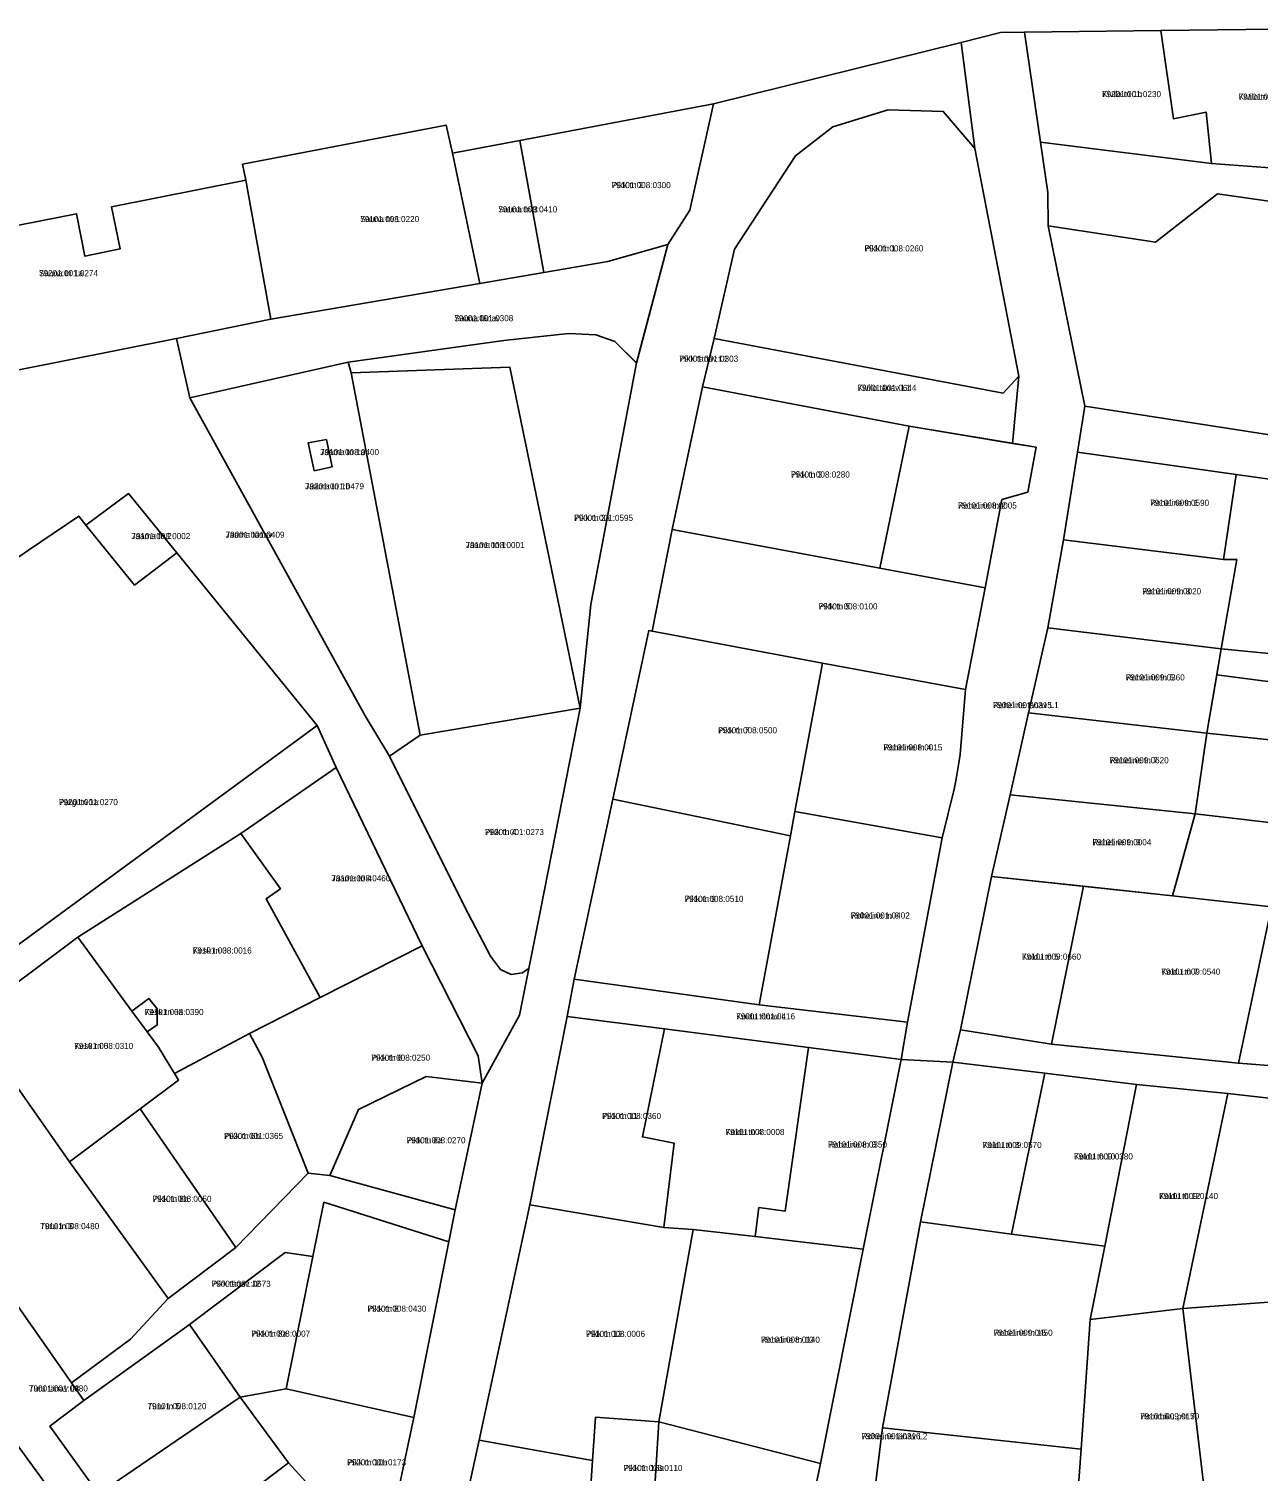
# Model space of a CAD drawing. Extents: x 587616 to 632239, y 6547421 to 6574977.
# Drawn here: x 611846.3 to 612148.7, y 6570989.5 to 6571344.3 of the extents above; entities that cross this region are included whole.
import ezdxf

# ---------------------------------------------------------------- set-up
doc = ezdxf.new("R2010")
doc.units = 0
for name, color, linetype in [('L_AADRESS', 7, 'Continuous'), ('PIIR', 7, 'Continuous'), ('TUNNUS', 7, 'Continuous')]:
    doc.layers.add(name, color=color, linetype=linetype)

msp = doc.modelspace()

# ---------------------------------------------------------------- linework, layer by layer
at = {"layer": 'PIIR'}
for points in [[(612159.63, 6571344.34), (612124.75, 6571343.9), (612091.19, 6571343.49), (612085.34, 6571343.42), (612075.6, 6571341), (612014.71, 6571325.9), (611967.08, 6571316.89), (611950.53, 6571313.76), (611948.93, 6571320.68), (611898.86, 6571311.01), (611899.64, 6571307.09), (611866.62, 6571300.55), (611868.7, 6571290.18), (611860.08, 6571288.4), (611857.99, 6571298.86), (611793.18, 6571286.08), (611716.96, 6571271.05), (611686.66, 6571259.35), (611655.98, 6571247.48), (611408.02, 6571196), (611286.97, 6571135.57), (611224.5, 6571123.76), (611132.41, 6571106.34)], [(611934.47, 6570972.06), (611940.95, 6571002.62), (611949.58, 6571045.84), (611951.18, 6571053.73), (611957.8, 6571084.94), (611966.95, 6571101.66), (611969.27, 6571113.14), (611972.25, 6571127.9), (611981.93, 6571177.16), (611984.57, 6571202.68), (611995.77, 6571262.19), (612003.5, 6571291.27), (612008.92, 6571299.72), (612014.71, 6571325.9), (612075.6, 6571341), (612079.03, 6571314.89), (612071.23, 6571324), (612057.68, 6571324.43), (612044.08, 6571320.27), (612034.89, 6571313.06), (612019.91, 6571290.15), (612014.85, 6571268.18), (612011.99, 6571256.26), (612004.56, 6571221.13), (611999.58, 6571196.13), (611998.79, 6571196.26), (611989.91, 6571154.82), (611980.45, 6571110.48), (611978.73, 6571101.33), (611969.53, 6571054.97), (611957.02, 6570997.08), (611949.31, 6570961.41)], [(612225.36, 6571291.39), (612138.73, 6571303.77), (612123.46, 6571291.85), (612097.01, 6571295.89), (612096.94, 6571304.04), (612095.13, 6571316.44), (612137.22, 6571311.19), (612161.56, 6571309.44)], [(611840.92, 6571259.86), (611882.6, 6571268.16), (611885.88, 6571253.53), (611929.02, 6571175.32), (611935.02, 6571165.42), (611953.43, 6571128.42), (611959.81, 6571116.13), (611962.28, 6571112.89), (611964.94, 6571111.65), (611967.61, 6571112.03), (611969.27, 6571113.14), (611966.95, 6571101.66), (611957.8, 6571084.94), (611956.82, 6571091.68), (611943.03, 6571118.7), (611921.84, 6571162.58), (611917.24, 6571172.94), (611882.65, 6571215.41), (611870.8, 6571229.97), (611860.33, 6571222.25), (611858.54, 6571224.47), (611846.22, 6571216.07)], [(612162.03, 6571232.07), (612143.29, 6571234.7), (612104.25, 6571240.15), (612106.04, 6571251.52), (612176.89, 6571240.53)], [(611596.46, 6570962.66), (611673.74, 6570998.74), (611694.36, 6571008.59), (611717.91, 6571025.71), (611724.56, 6571030.16), (611783.89, 6571075.21), (611793.48, 6571082.19), (611917.24, 6571172.94), (611921.84, 6571162.58), (611898.4, 6571146.35), (611858.29, 6571120.81), (611831.79, 6571100.99), (611806.97, 6571082.36), (611790.89, 6571067.49), (611746.86, 6571034.54), (611745.56, 6571036.48), (611716.21, 6571014.5), (611694, 6570998.65), (611656.11, 6570977.68)], [(612168.14, 6571079.36), (612141.26, 6571082.37), (612118.78, 6571084.6), (612096.24, 6571087.37), (612073.58, 6571090.09), (612075.45, 6571098.01), (612097.83, 6571094.53), (612143.83, 6571089.87), (612165.05, 6571088.21)]]:
    msp.add_lwpolyline(points, dxfattribs=at)
for points in [[(612091.19, 6571343.49), (612124.75, 6571343.9), (612127.87, 6571322.2), (612135.9, 6571323.86), (612137.22, 6571311.19), (612095.13, 6571316.44)], [(612159.63, 6571344.34), (612161.56, 6571309.44), (612137.22, 6571311.19), (612135.9, 6571323.86), (612127.87, 6571322.2), (612124.75, 6571343.9)], [(612075.6, 6571341), (612085.34, 6571343.42), (612091.19, 6571343.49), (612095.13, 6571316.44), (612096.94, 6571304.04), (612097.01, 6571295.89), (612106.04, 6571251.52), (612104.25, 6571240.15), (612100.81, 6571218.65), (612096.94, 6571196.98), (612092.17, 6571176.07), (612087.66, 6571155.9), (612083.07, 6571135.78), (612075.45, 6571098.01), (612073.58, 6571090.09), (612060.85, 6571090.75), (612062.4, 6571099.89), (612071, 6571145.29), (612073.95, 6571157.25), (612074.3, 6571159.32), (612075.06, 6571163.71), (612075.41, 6571165.77), (612076.7, 6571181.82), (612081.51, 6571206.81), (612085.65, 6571228.52), (612092, 6571230.37), (612094.06, 6571241.4), (612088.25, 6571242.34), (612089.83, 6571258.89), (612079.03, 6571314.89)], [(612014.71, 6571325.9), (612008.92, 6571299.72), (612003.5, 6571291.27), (611988.74, 6571287.06), (611972.99, 6571284.39), (611967.08, 6571316.89)], [(612019.91, 6571290.15), (612034.89, 6571313.06), (612044.08, 6571320.27), (612057.68, 6571324.43), (612071.23, 6571324), (612079.03, 6571314.89), (612089.83, 6571258.89), (612085.97, 6571254.71), (612014.85, 6571268.18)], [(611898.86, 6571311.01), (611948.93, 6571320.68), (611950.53, 6571313.76), (611957.26, 6571281.67), (611905.83, 6571272.89), (611899.64, 6571307.09)], [(611950.53, 6571313.76), (611967.08, 6571316.89), (611972.99, 6571284.39), (611957.26, 6571281.67)], [(611793.18, 6571286.08), (611857.99, 6571298.86), (611860.08, 6571288.4), (611868.7, 6571290.18), (611866.62, 6571300.55), (611899.64, 6571307.09), (611905.83, 6571272.89), (611882.6, 6571268.16), (611840.92, 6571259.86), (611828.55, 6571263.66), (611813.81, 6571271.14), (611804.44, 6571276), (611795.74, 6571278.98), (611794.13, 6571280.68)], [(612106.04, 6571251.52), (612097.01, 6571295.89), (612123.46, 6571291.85), (612138.73, 6571303.77), (612225.36, 6571291.39), (612223.39, 6571278.76), (612176.89, 6571240.53)], [(612003.5, 6571291.27), (611995.75, 6571262.11), (611990.43, 6571267.37), (611985.73, 6571269.08), (611979.04, 6571269.37), (611963.13, 6571267.64), (611924.82, 6571262.32), (611885.88, 6571253.53), (611882.6, 6571268.16), (611905.83, 6571272.89), (611957.26, 6571281.67), (611972.99, 6571284.39), (611988.74, 6571287.06)], [(611925.53, 6571259.72), (611924.82, 6571262.32), (611963.13, 6571267.64), (611979.04, 6571269.37), (611985.73, 6571269.08), (611990.43, 6571267.37), (611995.77, 6571262.19), (611984.57, 6571202.68), (611981.93, 6571177.16), (611964.57, 6571261.13)], [(612014.85, 6571268.18), (612085.97, 6571254.71), (612089.83, 6571258.89), (612088.25, 6571242.34), (612062.85, 6571246.54), (612011.99, 6571256.26)], [(611935.02, 6571165.42), (611929.02, 6571175.32), (611885.88, 6571253.53), (611924.82, 6571262.32), (611925.53, 6571259.72), (611942.56, 6571170.55)], [(611925.53, 6571259.72), (611964.57, 6571261.13), (611981.93, 6571177.16), (611942.56, 6571170.55)], [(612011.99, 6571256.26), (612062.85, 6571246.54), (612055.6, 6571211.61), (612004.56, 6571221.13)], [(612062.85, 6571246.54), (612094.06, 6571241.4), (612092, 6571230.37), (612085.65, 6571228.52), (612081.51, 6571206.81), (612055.6, 6571211.61)], [(611919.49, 6571243.26), (611920.89, 6571236.55), (611916.47, 6571235.62), (611914.98, 6571242.44)], [(611920.89, 6571236.55), (611919.49, 6571243.26), (611914.98, 6571242.44), (611916.47, 6571235.62)], [(612104.25, 6571240.15), (612143.29, 6571234.7), (612140.2, 6571213.8), (612100.81, 6571218.65)], [(612143.44, 6571213.75), (612140.2, 6571213.8), (612143.29, 6571234.7), (612162.03, 6571232.07), (612154.8, 6571190.35), (612139.63, 6571191.77)], [(611870.8, 6571229.97), (611882.65, 6571215.41), (611872.27, 6571207.47), (611860.33, 6571222.25)], [(611796.12, 6571181.57), (611846.22, 6571216.07), (611858.54, 6571224.47), (611860.33, 6571222.25), (611872.27, 6571207.47), (611882.65, 6571215.41), (611917.24, 6571172.94), (611793.48, 6571082.19), (611746.37, 6571145.45), (611778.84, 6571168.84), (611817.45, 6571116.23), (611834.77, 6571128.93)], [(612076.7, 6571181.82), (612041.51, 6571188.29), (611999.58, 6571196.13), (612004.56, 6571221.13), (612055.6, 6571211.61), (612081.51, 6571206.81)], [(612100.81, 6571218.65), (612140.2, 6571213.8), (612143.44, 6571213.75), (612139.63, 6571191.77), (612096.94, 6571196.98)], [(611998.79, 6571196.26), (611999.58, 6571196.13), (612041.51, 6571188.29), (612034.75, 6571151.78), (612033.64, 6571145.75), (611989.91, 6571154.82)], [(612096.94, 6571196.98), (612139.63, 6571191.77), (612136.06, 6571171.04), (612092.17, 6571176.07)], [(612139.63, 6571191.77), (612154.8, 6571190.35), (612169.4, 6571188.56), (612168.18, 6571181.54), (612138.54, 6571185.42)], [(612041.51, 6571188.29), (612076.7, 6571181.82), (612075.41, 6571165.77), (612075.06, 6571163.71), (612074.3, 6571159.32), (612073.95, 6571157.25), (612071, 6571145.29), (612034.75, 6571151.78)], [(612138.54, 6571185.42), (612168.18, 6571181.54), (612169.4, 6571188.56), (612183.24, 6571187.09), (612185.26, 6571186.86), (612181.01, 6571166.26), (612136.1, 6571171.05)], [(611935.02, 6571165.42), (611942.56, 6571170.55), (611981.93, 6571177.16), (611972.25, 6571127.9), (611969.27, 6571113.14), (611967.61, 6571112.03), (611964.94, 6571111.65), (611962.28, 6571112.89), (611959.81, 6571116.13), (611953.43, 6571128.42)], [(612092.17, 6571176.07), (612136.06, 6571171.04), (612133.18, 6571151.19), (612087.66, 6571155.9)], [(612176.78, 6571146.09), (612133.18, 6571151.19), (612136.06, 6571171.04), (612180.96, 6571166.26)], [(611904.64, 6571130.26), (611908.16, 6571132.77), (611898.4, 6571146.35), (611921.84, 6571162.58), (611943.03, 6571118.7), (611917.93, 6571105.96)], [(612083.07, 6571135.78), (612087.66, 6571155.9), (612133.18, 6571151.19), (612127.6, 6571131.03)], [(611989.91, 6571154.82), (612033.64, 6571145.75), (612025.98, 6571104.21), (611980.45, 6571110.48)], [(612033.64, 6571145.75), (612034.75, 6571151.78), (612071, 6571145.29), (612062.4, 6571099.89), (612025.98, 6571104.21)], [(612127.6, 6571131.03), (612133.18, 6571151.19), (612176.78, 6571146.09), (612173.72, 6571125.87), (612152, 6571128.31)], [(611898.4, 6571146.35), (611908.16, 6571132.77), (611904.64, 6571130.26), (611917.93, 6571105.96), (611900.56, 6571097.15), (611882.14, 6571087.28), (611878.17, 6571093.77), (611875.41, 6571097.52), (611877.86, 6571099.25), (611877.88, 6571103.19), (611875.82, 6571105.75), (611871.64, 6571102.65), (611858.29, 6571120.81)], [(612083.07, 6571135.78), (612105.76, 6571133.36), (612097.83, 6571094.53), (612075.45, 6571098.01)], [(612105.76, 6571133.36), (612127.6, 6571131.03), (612152, 6571128.31), (612143.83, 6571089.87), (612097.83, 6571094.53)], [(612152, 6571128.31), (612173.72, 6571125.87), (612165.05, 6571088.21), (612143.83, 6571089.87)], [(611842.9, 6571084.7), (611831.79, 6571100.99), (611858.29, 6571120.81), (611871.64, 6571102.65), (611875.41, 6571097.52), (611878.17, 6571093.77), (611882.14, 6571087.28), (611883.13, 6571085.66), (611873.63, 6571078.61), (611856.27, 6571065.58)], [(611903.65, 6571091.31), (611900.56, 6571097.15), (611917.93, 6571105.96), (611943.03, 6571118.7), (611956.82, 6571091.68), (611957.8, 6571084.94), (611944.06, 6571086.53), (611927.36, 6571078.47), (611920.34, 6571062.2), (611915.01, 6571062.81)], [(611980.45, 6571110.48), (612025.97, 6571104.21), (612062.4, 6571099.89), (612060.85, 6571090.75), (612038.12, 6571093.7), (612002.62, 6571098.26), (611978.73, 6571101.33)], [(611871.64, 6571102.65), (611875.82, 6571105.75), (611877.88, 6571103.19), (611877.86, 6571099.25), (611875.41, 6571097.52)], [(612002.62, 6571098.26), (611997.23, 6571071.68), (612005.06, 6571070.12), (612002.48, 6571049.41), (611969.53, 6571054.97), (611978.73, 6571101.33)], [(611915.01, 6571062.81), (611897.16, 6571044.45), (611873.63, 6571078.61), (611883.13, 6571085.66), (611882.14, 6571087.28), (611900.56, 6571097.15), (611903.65, 6571091.31)], [(612002.62, 6571098.26), (612038.12, 6571093.7), (612032.37, 6571053.43), (612025.9, 6571054.31), (612024.93, 6571047.15), (612009.68, 6571048.91), (612002.48, 6571049.41), (612005.06, 6571070.12), (611997.23, 6571071.68)], [(612060.85, 6571090.75), (612051.56, 6571044.07), (612024.93, 6571047.15), (612025.9, 6571054.31), (612032.37, 6571053.43), (612038.12, 6571093.7)], [(612060.85, 6571090.75), (612073.58, 6571090.09), (612065.63, 6571050.81), (612056.31, 6571000.15), (612052.02, 6570965.62), (612052.46, 6570959.45), (612053.64, 6570954.9), (612028.71, 6570932.34), (612041.01, 6570991.37), (612051.56, 6571044.07)], [(612073.58, 6571090.09), (612096.24, 6571087.37), (612087.99, 6571047.78), (612065.63, 6571050.81)], [(611842.9, 6571084.7), (611856.27, 6571065.58), (611880.56, 6571031.96), (611871.3, 6571021.89), (611856.76, 6571011.2), (611817.61, 6571067.01)], [(611920.34, 6571062.2), (611927.36, 6571078.47), (611944.06, 6571086.53), (611957.8, 6571084.94), (611951.18, 6571053.73)], [(612096.24, 6571087.37), (612118.78, 6571084.6), (612110.97, 6571044.82), (612087.99, 6571047.78)], [(612110.97, 6571044.82), (612118.78, 6571084.6), (612141.26, 6571082.37), (612130.2, 6571029.46), (612107.41, 6571026.75)], [(611790.89, 6571067.49), (611806.97, 6571082.36), (611817.61, 6571067.01), (611856.76, 6571011.2), (611859.81, 6571006.84), (611851.44, 6571000.55), (611863.4, 6570983.87), (611876.72, 6570966.16), (611901.68, 6570932.17), (611890.97, 6570930.92), (611875.82, 6570951.44), (611831.96, 6571011.62), (611818.65, 6571029.46)], [(612141.26, 6571082.37), (612168.14, 6571079.36), (612160.19, 6571031.69), (612130.2, 6571029.46)], [(611873.63, 6571078.61), (611897.16, 6571044.45), (611880.56, 6571031.96), (611856.27, 6571065.58)], [(611951.18, 6571053.73), (611949.58, 6571045.84), (611918.83, 6571055.61), (611916.14, 6571042.29), (611909.32, 6571043.26), (611885.83, 6571025.53), (611885.17, 6571025.05), (611859.81, 6571006.84), (611856.76, 6571011.2), (611871.3, 6571021.89), (611880.56, 6571031.96), (611897.16, 6571044.45), (611915.01, 6571062.81), (611920.34, 6571062.2)], [(611949.58, 6571045.84), (611940.95, 6571002.62), (611909.57, 6571009.68), (611916.14, 6571042.29), (611918.83, 6571055.61)], [(611969.53, 6571054.97), (612002.48, 6571049.41), (612009.68, 6571048.91), (612001.23, 6571001.62), (611985.7, 6571002.71), (611984.97, 6570992.06), (611957.02, 6570997.08)], [(612105.13, 6570994.86), (612056.31, 6571000.15), (612065.63, 6571050.81), (612087.99, 6571047.78), (612110.97, 6571044.82), (612107.41, 6571026.75)], [(612009.68, 6571048.91), (612024.93, 6571047.15), (612051.56, 6571044.07), (612041.01, 6570991.37), (612001.23, 6571001.62)], [(611885.83, 6571025.53), (611909.32, 6571043.26), (611916.14, 6571042.29), (611909.57, 6571009.68), (611898.26, 6571007.64)], [(612130.2, 6571029.46), (612160.19, 6571031.69), (612162.16, 6571031.85), (612167.56, 6570988.8), (612135.94, 6570980.88)], [(612135.94, 6570980.88), (612103.45, 6570971.53), (612105.13, 6570994.86), (612107.41, 6571026.75), (612130.2, 6571029.46)], [(611851.44, 6571000.55), (611859.81, 6571006.84), (611885.17, 6571025.05), (611885.83, 6571025.53), (611898.26, 6571007.64), (611863.4, 6570983.87)], [(611795.39, 6570960.29), (611811.73, 6570971.84), (611816.22, 6570999.65), (611831.96, 6571011.62), (611875.82, 6570951.44), (611843.11, 6570927.07), (611840.96, 6570929.94), (611836.93, 6570926.92), (611824.35, 6570917.49)], [(611910.15, 6570991.48), (611894.33, 6570979.5), (611876.72, 6570966.16), (611863.4, 6570983.87), (611898.26, 6571007.64)], [(611940.95, 6571002.62), (611934.47, 6570972.06), (611926.45, 6570973.62), (611910.15, 6570991.48), (611898.26, 6571007.64), (611909.57, 6571009.68)], [(611984.97, 6570992.06), (611985.7, 6571002.71), (612001.23, 6571001.62), (611999.74, 6570976.44), (611983.93, 6570977.11)], [(612001.23, 6571001.62), (612041.01, 6570991.37), (612028.71, 6570932.34), (612024.75, 6570928.62), (612018.15, 6570929.92), (612003.68, 6570932.78), (612011.99, 6570975.43), (611999.74, 6570976.44)], [(612103.45, 6570971.53), (612053.64, 6570954.9), (612052.46, 6570959.45), (612052.02, 6570965.62), (612054.9, 6570988.79), (612056.31, 6571000.15), (612105.13, 6570994.86)], [(611949.31, 6570961.41), (611957.02, 6570997.08), (611984.97, 6570992.06), (611983.93, 6570977.11), (611965.98, 6570957.18), (611950.81, 6570957.97)], [(611910.15, 6570991.48), (611926.45, 6570973.62), (611934.47, 6570972.06), (611937.58, 6570971.4), (611933.53, 6570951.02), (611931.49, 6570948.39), (611917.69, 6570942.27), (611894.33, 6570979.5)]]:
    msp.add_lwpolyline(points, close=True, dxfattribs=at)

# ---------------------------------------------------------------- texts
at = {"layer": 'L_AADRESS'}
for s, p in [('Kivilo tn 1b', (612110.31, 6571327.54)), ('Kivilo tn 1', (612143.9, 6571326.89)), ('Pikk tn 2', (611989.67, 6571305.15)), ('Sauna tn 1', (611927.8, 6571296.79)), ('Sauna tn 3', (611961.76, 6571299.17)), ('Pikk tn 1', (612051.84, 6571289.57)), ('Sauna tn 1a', (611848.78, 6571283.48)), ('Sauna tänav', (611950.95, 6571272.4)), ('Pikk tänav L1', (612006.28, 6571262.43)), ('Kivilo tänav L1', (612050.14, 6571255.26)), ('Jaama tn 1a', (611917.93, 6571239.45)), ('Pikk tn 3', (612033.75, 6571233.94)), ('Jaama tn 1b', (611914.22, 6571231.04)), ('Roheline tn 2', (612074.83, 6571226.31)), ('Roheline tn 1', (612122.14, 6571226.98)), ('Pikk tn 2a', (611980.42, 6571223.27)), ('Jaama tn 2', (611871.49, 6571218.78)), ('Jaama tänav', (611894.67, 6571219.12)), ('Jaama tn 1', (611953.73, 6571216.58)), ('Roheline tn 3', (612120.18, 6571205.21)), ('Pikk tn 5', (612040.56, 6571201.48)), ('Roheline tn 5', (612116.14, 6571184.01)), ('Roheline tänav L1', (612083.45, 6571177.19)), ('Pikk tn 7', (612015.84, 6571171.01)), ('Roheline tn 4', (612056.51, 6571166.79)), ('Roheline tn 7', (612112.19, 6571163.63)), ('Pargi tn 1a', (611853.68, 6571153.33)), ('Pikk tn 4', (611958.48, 6571145.96)), ('Roheline tn 9', (612107.93, 6571143.46)), ('Jaama tn 4', (611920.71, 6571134.59)), ('Pikk tn 9', (612007.58, 6571129.52)), ('Roheline tn 6', (612048.49, 6571125.43)), ('Kesk tn 3', (611886.61, 6571116.82)), ('Koidu tn 5', (612090.61, 6571115.31)), ('Koidu tn 7', (612124.89, 6571111.62)), ('Kesk tn 3a', (611874.76, 6571101.68)), ('Koidu tänav L1', (612020.29, 6571100.62)), ('Kesk tn 5', (611857.46, 6571093.33)), ('Pikk tn 6', (611930.5, 6571090.45)), ('Pikk tn 11', (611987.3, 6571076.1)), ('Pikk tn 6b', (611894.32, 6571071.19)), ('Pikk tn 6a', (611939.21, 6571070.13)), ('Koidu tn 4', (612017.67, 6571072.16)), ('Roheline tn 8', (612042.89, 6571069.08)), ('Koidu tn 8', (612080.94, 6571068.97)), ('Koidu tn 10', (612103.39, 6571066.14)), ('Pikk tn 8b', (611876.71, 6571055.71)), ('Koidu tn 12', (612124.33, 6571056.41)), ('Turu tn 3', (611849.09, 6571049)), ('Pikk tänav J2', (611891.26, 6571034.82)), ('Pikk tn 8', (611929.57, 6571028.69)), ('Roheline tn 15', (612083.64, 6571022.78)), ('Pikk tn 8a', (611900.98, 6571022.55)), ('Pikk tn 13', (611983.35, 6571022.49)), ('Roheline tn 10', (612026.39, 6571021.06)), ('Turu tänav L3', (611846.29, 6571009.05)), ('Turu tn 5', (611875.46, 6571004.7)), ('Hommiku pst 5', (612119.7, 6571002.21)), ('Roheline tänav L2', (612051.14, 6570997.32)), ('Pikk tn 10a', (611924.58, 6570990.87)), ('Pikk tn 15a', (611992.58, 6570989.49))]:
    msp.add_text(s, height=1.5, dxfattribs=at).set_placement(p)
at = {"layer": 'TUNNUS'}
for s, p in [('79201:001:0230', (612110.31, 6571327.54)), ('79101:009:0003', (612143.9, 6571326.89)), ('79101:008:0300', (611989.67, 6571305.15)), ('79101:008:0220', (611927.8, 6571296.79)), ('79101:008:0410', (611961.76, 6571299.17)), ('79101:008:0260', (612051.84, 6571289.57)), ('79201:001:0274', (611848.78, 6571283.48)), ('79001:001:0308', (611950.95, 6571272.4)), ('79001:001:0303', (612006.28, 6571262.43)), ('79001:001:0644', (612050.14, 6571255.26)), ('79101:008:0400', (611917.93, 6571239.45)), ('79101:008:0280', (612033.75, 6571233.94)), ('79201:001:0479', (611914.22, 6571231.04)), ('79101:008:0005', (612074.83, 6571226.31)), ('79101:009:0590', (612122.14, 6571226.98)), ('79001:001:0595', (611980.42, 6571223.27)), ('79101:008:0002', (611871.49, 6571218.78)), ('79001:001:0409', (611894.67, 6571219.12)), ('79101:008:0001', (611953.73, 6571216.58)), ('79101:009:0020', (612120.18, 6571205.21)), ('79101:008:0100', (612040.56, 6571201.48)), ('79101:009:0360', (612116.14, 6571184.01)), ('79001:001:0315', (612083.45, 6571177.19)), ('79101:008:0500', (612015.84, 6571171.01)), ('79101:008:0015', (612056.51, 6571166.79)), ('79101:009:0620', (612112.19, 6571163.63)), ('79201:001:0270', (611853.68, 6571153.33)), ('79201:001:0273', (611958.48, 6571145.96)), ('79101:009:0004', (612107.93, 6571143.46)), ('79101:008:0460', (611920.71, 6571134.59)), ('79101:008:0510', (612007.58, 6571129.52)), ('79001:001:0402', (612048.49, 6571125.43)), ('79101:008:0016', (611886.61, 6571116.82)), ('79101:009:0660', (612090.61, 6571115.31)), ('79101:009:0540', (612124.89, 6571111.62)), ('79101:008:0390', (611874.76, 6571101.68)), ('79001:001:0416', (612020.29, 6571100.62)), ('79101:008:0310', (611857.46, 6571093.33)), ('79101:008:0250', (611930.5, 6571090.45)), ('79101:008:0360', (611987.3, 6571076.1)), ('79201:001:0365', (611894.32, 6571071.19)), ('79101:008:0270', (611939.21, 6571070.13)), ('79101:008:0008', (612017.67, 6571072.16)), ('79101:008:0350', (612042.89, 6571069.08)), ('79101:009:0570', (612080.94, 6571068.97)), ('79101:009:0380', (612103.39, 6571066.14)), ('79101:008:0050', (611876.71, 6571055.71)), ('79101:009:0140', (612124.33, 6571056.41)), ('79101:008:0480', (611849.09, 6571049)), ('79001:001:0673', (611891.26, 6571034.82)), ('79101:008:0430', (611929.57, 6571028.69)), ('79101:009:0450', (612083.64, 6571022.78)), ('79101:008:0007', (611900.98, 6571022.55)), ('79101:008:0006', (611983.35, 6571022.49)), ('79101:008:0140', (612026.39, 6571021.06)), ('79001:001:0480', (611846.29, 6571009.05)), ('79101:008:0120', (611875.46, 6571004.7)), ('79101:009:0170', (612119.7, 6571002.21)), ('79001:001:0316', (612051.14, 6570997.32)), ('79201:001:0173', (611924.58, 6570990.87)), ('79101:008:0110', (611992.58, 6570989.49))]:
    msp.add_text(s, height=1.5, dxfattribs=at).set_placement(p)

doc.saveas('drawing.dxf')
